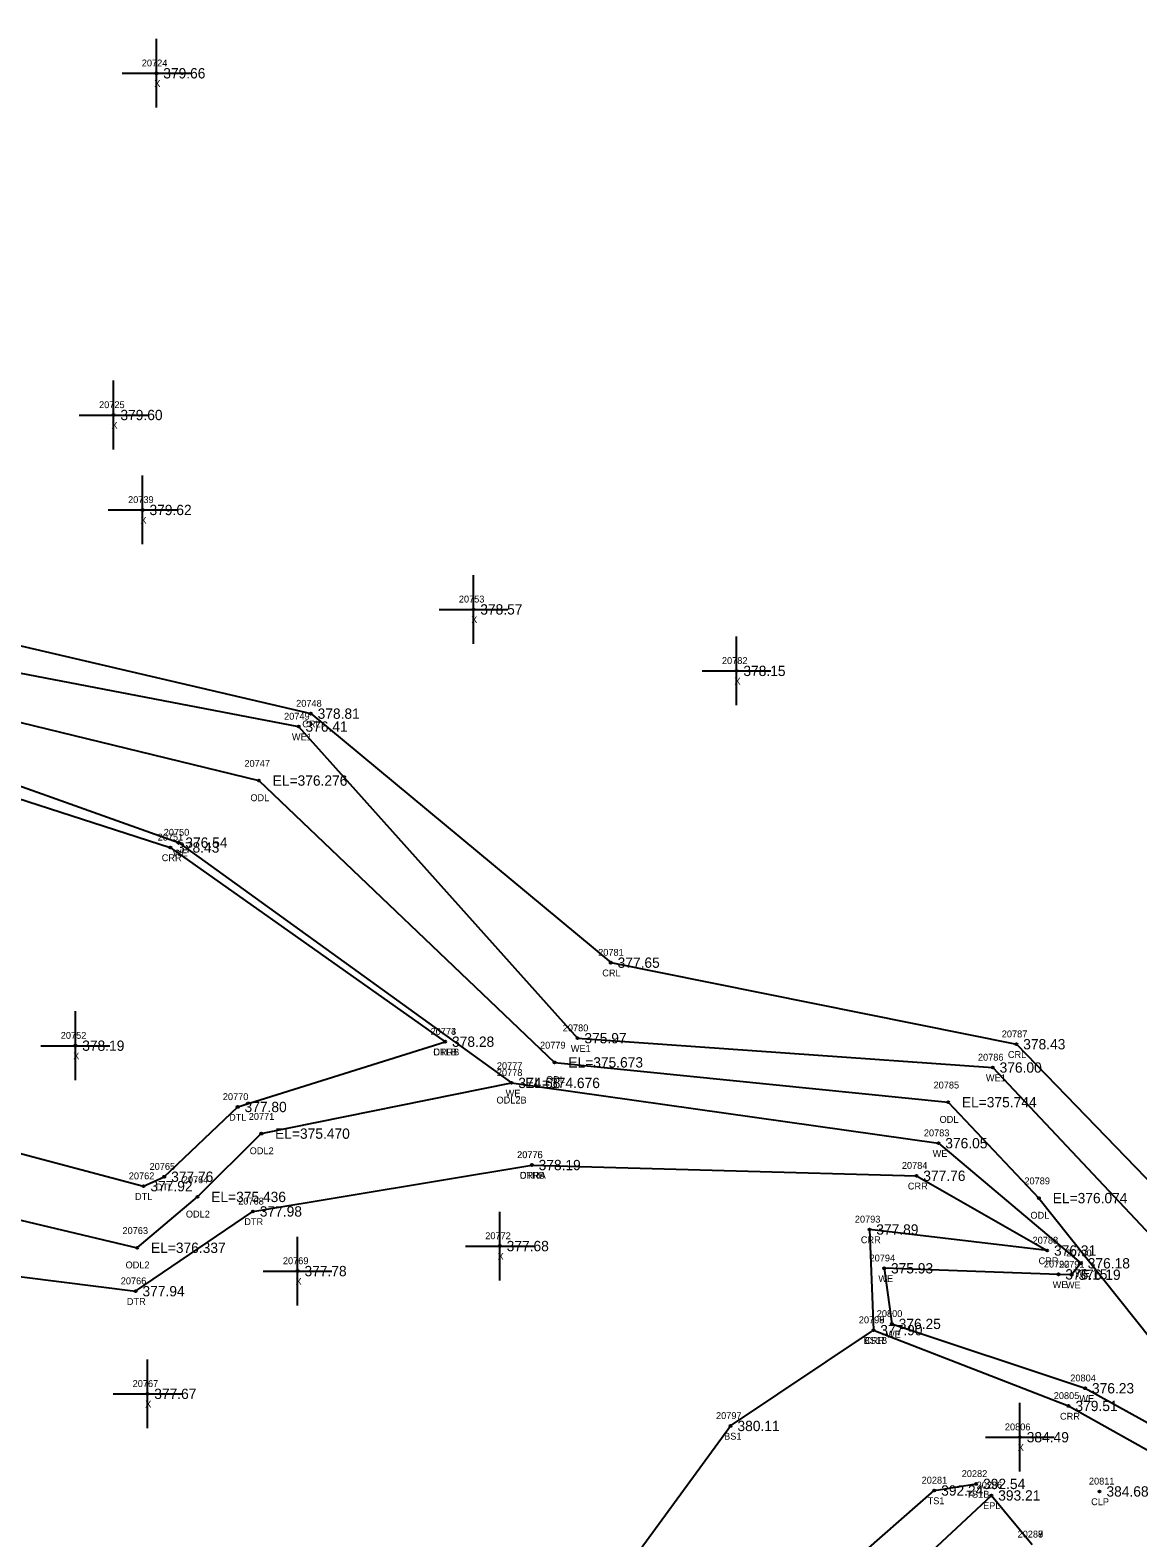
# Model space of a CAD drawing. Extents: x 2116373 to 2118139, y 979529 to 981026.
# Drawn here: x 2117180.8 to 2117341.9, y 980127.3 to 980346.7 of the extents above; entities that cross this region are included whole.
import ezdxf

# ---------------------------------------------------------------- set-up
doc = ezdxf.new("R2010")
doc.units = 0
for name, color, linetype in [('RD_DTM_BkLn2', 7, 'Continuous'), ('RD_DTM_BkLn_txCode', 7, 'Continuous'), ('RD_EX_H2O', 7, 'Continuous'), ('RD_EX_H2O_txCode', 7, 'Continuous'), ('RD_EX_Misc', 7, 'Continuous'), ('RD_EX_Misc_txCode', 7, 'Continuous'), ('RD_EX_Road', 7, 'Continuous'), ('RD_EX_Road_txCode', 7, 'Continuous'), ('RD_EX_TX_H2O_ELEV', 7, 'Continuous'), ('RD_EX_TX_Misc_ELEV', 7, 'Continuous'), ('RD_EX_TX_Road_ELEV', 7, 'Continuous'), ('RD_HC_Survey_ELEV', 7, 'Continuous'), ('RD_HC_Survey_txCode', 7, 'Continuous'), ('RD_SMD_Locator', 7, 'Continuous')]:
    doc.layers.add(name, color=color, linetype=linetype)

msp = doc.modelspace()

# ---------------------------------------------------------------- linework, layer by layer
at = {"layer": 'RD_DTM_BkLn2'}
for points in [[(2117265.44, 980120.03), (2117282.69, 980143.6), (2117303.47, 980157.54)], [(2116410.78, 979641.79), (2116465.45, 979654.97), (2116518.83, 979664.89), (2116614.96, 979683.75), (2116663.75, 979692.58), (2116713.02, 979705.22), (2116760.07, 979721.97), (2116804.88, 979741.47), (2116850.79, 979761.38), (2116894.83, 979783.88), (2116937.98, 979807.44), (2116977.39, 979833.6), (2117020.56, 979865.29), (2117056.86, 979896.38), (2117094.29, 979932.2), (2117168.14, 979997.38), (2117238.71, 980069.61), (2117312.33, 980134.21), (2117318.43, 980135.16)]]:
    msp.add_lwpolyline(points, dxfattribs=at)
at = {"layer": 'RD_EX_H2O'}
for points in [[(2117055.27, 980533.4), (2117084.87, 980468.5), (2117113.12, 980396.82), (2117150.26, 980360.48), (2117172.14, 980330.53), (2117167.4, 980300.56), (2117152, 980282.05), (2117153.33, 980268.31), (2117164.01, 980260.72), (2117221.6, 980247.26), (2117265.25, 980211.02), (2117324.27, 980199.15), (2117347.37, 980175.31), (2117365.85, 980182.55), (2117389.45, 980162.29), (2117399.63, 980142.01), (2117411.26, 980120.88), (2117420.42, 980068.64), (2117446.24, 980057.21), (2117497.11, 980045.39), (2117594.71, 979999.33), (2117646.33, 979985.56), (2117750.91, 980032.44), (2117805.09, 980018.87)], [(2117050.82, 980532.07), (2117080.88, 980466.55), (2117110.64, 980395.71), (2117144.25, 980349.68), (2117164.75, 980337.49), (2117167.1, 980320.28), (2117162.85, 980307.87), (2117148.28, 980284.4), (2117152.02, 980266.59), (2117158.19, 980257.22), (2117219.84, 980245.38), (2117260.42, 980200.03), (2117320.83, 980195.76), (2117348.44, 980166.4)], [(2117046.35, 980528.47), (2117072.74, 980464.26), (2117103.18, 980398.05), (2117142.6, 980347.56), (2117158.28, 980333.4), (2117157.84, 980320.26), (2117155.72, 980311.74), (2117145.74, 980285.73), (2117146.15, 980263.73), (2117154.31, 980252.06), (2117214.06, 980237.52), (2117257.08, 980196.51), (2117314.34, 980190.71), (2117327.56, 980176.76), (2117343.89, 980156.23)], [(2117042.29, 980526.09), (2117065.56, 980461.15), (2117099.14, 980397), (2117139.48, 980344.65), (2117153.05, 980329.52), (2117152.49, 980324.98), (2117153.14, 980319.82), (2117152.6, 980312.45), (2117140.5, 980286.71), (2117130.05, 980269.91), (2117147.41, 980248.1), (2117202.36, 980228.49), (2117250.8, 980193.52), (2117312.93, 980184.75), (2117333.66, 980167.27), (2117332.31, 980165.61), (2117330.39, 980165.66), (2117305.03, 980166.54), (2117306.15, 980158.45), (2117334.27, 980149.08), (2117359.88, 980134.92)], [(2117031.59, 980522.05), (2117061.22, 980460.91), (2117085.86, 980397.22), (2117136.43, 980344.22), (2117150.07, 980329.14), (2117146.87, 980313.29), (2117136.68, 980286.81), (2117127.11, 980271.21), (2117134.99, 980253.7), (2117146.93, 980245.3), (2117201.17, 980227.79), (2117241.16, 980199.52)], [(2117108.2, 980200.33), (2117129.82, 980185.32), (2117196.35, 980169.53), (2117205.12, 980176.93), (2117214.41, 980186.14), (2117250.8, 980193.52)], [(2117108.2, 980200.33), (2117119.12, 980172.91), (2117196.12, 980163.21), (2117213.19, 980174.82), (2117253.76, 980181.57)], [(2117108.2, 980200.33), (2117128.09, 980196.89), (2117197.27, 980178.49), (2117200.29, 980179.87), (2117210.97, 980190.02), (2117241.16, 980199.52)], [(2117253.76, 980181.57), (2117309.73, 980180.01), (2117328.75, 980169.13), (2117302.89, 980172.19), (2117303.47, 980157.54), (2117331.87, 980146.51), (2117356.54, 980132.72), (2117379.52, 980112.38), (2117402.94, 980061.78), (2117424.79, 980029.41), (2117490.12, 980015.27), (2117551.05, 979984.61)]]:
    msp.add_lwpolyline(points, dxfattribs=at)
at = {"layer": 'RD_EX_Misc'}
for p, q in [((2117199.14, 980335.45), (2117199.14, 980345.45)), ((2117194.14, 980340.45), (2117204.14, 980340.45)), ((2117192.91, 980285.72), (2117192.91, 980295.72)), ((2117187.91, 980290.72), (2117197.91, 980290.72)), ((2117197.14, 980271.9), (2117197.14, 980281.9)), ((2117192.14, 980276.9), (2117202.14, 980276.9)), ((2117245.27, 980257.43), (2117245.27, 980267.43)), ((2117240.27, 980262.43), (2117250.27, 980262.43)), ((2117283.55, 980248.48), (2117283.55, 980258.48)), ((2117278.55, 980253.48), (2117288.55, 980253.48)), ((2117187.35, 980193.94), (2117187.35, 980203.94)), ((2117182.35, 980198.94), (2117192.35, 980198.94)), ((2117249.11, 980164.78), (2117249.11, 980174.78)), ((2117219.69, 980161.14), (2117219.69, 980171.14)), ((2117244.11, 980169.78), (2117254.11, 980169.78)), ((2117214.69, 980166.14), (2117224.69, 980166.14)), ((2117197.83, 980143.27), (2117197.83, 980153.27)), ((2117192.83, 980148.27), (2117202.83, 980148.27)), ((2117324.78, 980136.96), (2117324.78, 980146.96)), ((2117319.78, 980141.96), (2117329.78, 980141.96))]:
    msp.add_line(p, q, dxfattribs=at)
at = {"layer": 'RD_EX_Road'}
msp.add_lwpolyline([(2116412.2, 979638.84), (2116468.17, 979651.36), (2116519.2, 979662.5), (2116617.24, 979678.85), (2116665.51, 979689.1), (2116714.23, 979702.46), (2116761.42, 979719.35), (2116806.99, 979737.42), (2116852.23, 979758.11), (2116896.57, 979780.91), (2116939.1, 979805.52), (2116978.46, 979832.1), (2117021.29, 979863.87), (2117058.15, 979895.61), (2117096.06, 979930.47), (2117170.14, 979995.71), (2117244.91, 980062.82), (2117320.63, 980133.49), (2117326.56, 980126.36)], dxfattribs=at)
at = {"layer": 'RD_SMD_Locator'}
for centre in [(2117199.14, 980340.45), (2117192.91, 980290.72), (2117197.14, 980276.9), (2117245.27, 980262.43), (2117283.55, 980253.48), (2117221.6, 980247.26), (2117219.84, 980245.38), (2117214.06, 980237.52), (2117201.17, 980227.79), (2117202.36, 980228.49), (2117265.25, 980211.02), (2117187.35, 980198.94), (2117241.16, 980199.52), (2117241.16, 980199.52), (2117260.42, 980200.03), (2117324.27, 980199.15), (2117257.08, 980196.51), (2117320.83, 980195.76), (2117250.8, 980193.52), (2117250.8, 980193.52), (2117210.97, 980190.02), (2117314.34, 980190.71), (2117214.41, 980186.14), (2117312.93, 980184.75), (2117253.76, 980181.57), (2117253.76, 980181.57), (2117200.29, 980179.87), (2117309.73, 980180.01), (2117197.27, 980178.49), (2117205.12, 980176.93), (2117327.56, 980176.76), (2117213.19, 980174.82), (2117302.89, 980172.19), (2117196.35, 980169.53), (2117249.11, 980169.78), (2117328.75, 980169.13), (2117219.69, 980166.14), (2117305.03, 980166.54), (2117333.66, 980167.27), (2117330.39, 980165.66), (2117332.31, 980165.61), (2117196.12, 980163.21), (2117303.47, 980157.54), (2117303.47, 980157.54), (2117306.15, 980158.45), (2117197.83, 980148.27), (2117334.27, 980149.08), (2117331.87, 980146.51), (2117282.69, 980143.6), (2117324.78, 980141.96), (2117318.43, 980135.16), (2117312.33, 980134.21), (2117320.63, 980133.49), (2117336.38, 980134.07)]:
    msp.add_circle(centre, 0.15, dxfattribs=at)

# ---------------------------------------------------------------- texts
at = {"layer": 'RD_DTM_BkLn_txCode'}
for s, p in [('20798', (2117301.35, 980158.54)), ('BS1B', (2117302.06, 980155.54)), ('20797', (2117280.57, 980144.6)), ('BS1', (2117281.75, 980141.6)), ('20281', (2117310.49, 980135.21)), ('20282', (2117316.32, 980136.16)), ('TS1', (2117311.36, 980132.21)), ('TS1B', (2117317, 980133.16))]:
    msp.add_text(s, height=1, dxfattribs=at).set_placement(p)
at = {"layer": 'RD_EX_H2O_txCode'}
for s, p in [('20748', (2117219.48, 980248.26)), ('20749', (2117217.72, 980246.38)), ('CRL', (2117220.37, 980245.26)), ('WE1', (2117218.86, 980243.38)), ('20747', (2117211.95, 980239.52)), ('ODL', (2117212.82, 980234.52)), ('20751', (2117199.33, 980228.79)), ('20750', (2117200.21, 980229.49)), ('WE', (2117201.53, 980226.49)), ('CRR', (2117199.92, 980225.79)), ('20781', (2117263.42, 980212.02)), ('CRL', (2117264.02, 980209.02)), ('20773', (2117239.04, 980200.52)), ('20774', (2117239.04, 980200.52)), ('20780', (2117258.27, 980201.03)), ('20787', (2117322.15, 980200.15)), ('20779', (2117254.96, 980198.51)), ('WE1', (2117259.44, 980198.03)), ('CRRB', (2117239.43, 980197.52)), ('DTLB', (2117239.44, 980197.52)), ('20777', (2117248.68, 980195.52)), ('20786', (2117318.68, 980196.76)), ('CRL', (2117323.04, 980197.15)), ('20778', (2117248.68, 980194.52)), ('ODL', (2117255.84, 980193.51)), ('WE1', (2117319.84, 980193.76)), ('WE', (2117249.96, 980191.52)), ('20785', (2117312.22, 980192.71)), ('20770', (2117208.81, 980191.02)), ('ODL2B', (2117248.63, 980190.52)), ('DTL', (2117209.72, 980188.02)), ('20771', (2117212.58, 980188.14)), ('ODL', (2117313.1, 980187.71)), ('20783', (2117310.81, 980185.75)), ('ODL2', (2117212.72, 980183.14)), ('20776', (2117251.62, 980182.57)), ('20775', (2117251.64, 980182.57)), ('WE', (2117312.09, 980182.75)), ('20765', (2117198.15, 980180.87)), ('20784', (2117307.61, 980181.01)), ('20762', (2117195.13, 980179.49)), ('20764', (2117202.98, 980178.93)), ('CRRA', (2117252.02, 980179.57)), ('DTRB', (2117252.02, 980179.57)), ('CRR', (2117308.48, 980178.01)), ('20789', (2117325.44, 980178.76)), ('DTL', (2117196.03, 980176.49)), ('DTL', (2117199.05, 980177.87)), ('20768', (2117211.05, 980175.82)), ('ODL2', (2117203.43, 980173.93)), ('ODL', (2117326.32, 980173.76)), ('20763', (2117194.21, 980171.53)), ('DTR', (2117211.93, 980172.82)), ('20793', (2117300.77, 980173.19)), ('CRR', (2117301.64, 980170.19)), ('20788', (2117326.63, 980170.13)), ('20794', (2117302.91, 980167.54)), ('CRR', (2117327.5, 980167.13)), ('20790', (2117331.51, 980168.27)), ('ODL2', (2117194.66, 980166.53)), ('20792', (2117328.27, 980166.66)), ('20791', (2117330.47, 980166.61)), ('WE', (2117332.82, 980165.27)), ('20766', (2117193.96, 980164.21)), ('WE', (2117304.19, 980164.54)), ('WE', (2117329.55, 980163.66)), ('WE', (2117331.47, 980163.61)), ('DTR', (2117194.85, 980161.21)), ('20799', (2117301.35, 980158.54)), ('20800', (2117303.96, 980159.45)), ('WE', (2117305.31, 980156.45)), ('CRR', (2117302.22, 980155.54)), ('20804', (2117332.12, 980150.08)), ('20805', (2117329.71, 980147.51)), ('WE', (2117333.43, 980147.08)), ('CRR', (2117330.62, 980144.51))]:
    msp.add_text(s, height=1, dxfattribs=at).set_placement(p)
at = {"layer": 'RD_EX_Misc_txCode'}
for s, p in [('20724', (2117197.02, 980341.45)), ('X', (2117198.83, 980338.45)), ('20725', (2117190.8, 980291.72)), ('X', (2117192.6, 980288.72)), ('20739', (2117195.02, 980277.9)), ('X', (2117196.82, 980274.9)), ('20753', (2117243.15, 980263.43)), ('X', (2117244.95, 980260.43)), ('20782', (2117281.43, 980254.48)), ('X', (2117283.24, 980251.48)), ('20752', (2117185.23, 980199.94)), ('X', (2117187.04, 980196.94)), ('20772', (2117246.99, 980170.78)), ('20769', (2117217.55, 980167.14)), ('X', (2117248.79, 980167.78)), ('X', (2117219.38, 980164.14)), ('20767', (2117195.69, 980149.27)), ('X', (2117197.51, 980146.27)), ('20806', (2117322.6, 980142.96)), ('X', (2117324.47, 980139.96))]:
    msp.add_text(s, height=1, dxfattribs=at).set_placement(p)
at = {"layer": 'RD_EX_Road_txCode'}
for s, p in [('20286', (2117318.49, 980134.49)), ('EPL', (2117319.43, 980131.49)), ('20287', (2117324.45, 980127.36)), ('20288', (2117324.45, 980127.36))]:
    msp.add_text(s, height=1, dxfattribs=at).set_placement(p)
at = {"layer": 'RD_EX_TX_H2O_ELEV'}
for s, p in [('378.81', (2117222.6, 980246.51)), ('376.41', (2117220.84, 980244.63)), ('EL=376.276', (2117216.06, 980236.77)), ('378.43', (2117202.17, 980227.04)), ('376.54', (2117203.36, 980227.74)), ('377.65', (2117266.25, 980210.27)), ('378.28', (2117242.16, 980198.77)), ('378.28', (2117242.16, 980198.77)), ('375.97', (2117261.42, 980199.28)), ('378.43', (2117325.27, 980198.4)), ('EL=375.673', (2117259.08, 980195.76)), ('376.00', (2117321.83, 980195.01)), ('374.68', (2117251.8, 980192.77)), ('EL=374.676', (2117252.8, 980192.77)), ('377.80', (2117211.97, 980189.27)), ('EL=375.744', (2117316.34, 980189.96)), ('EL=375.470', (2117216.41, 980185.39)), ('376.05', (2117313.93, 980184)), ('378.19', (2117254.76, 980180.82)), ('378.19', (2117254.76, 980180.82)), ('377.92', (2117198.27, 980177.74)), ('377.76', (2117201.29, 980179.12)), ('377.76', (2117310.73, 980179.26)), ('EL=375.436', (2117207.12, 980176.18)), ('EL=376.074', (2117329.56, 980176.01)), ('377.98', (2117214.19, 980174.07)), ('377.89', (2117303.89, 980171.44)), ('EL=376.337', (2117198.35, 980168.78)), ('376.31', (2117329.75, 980168.38)), ('376.18', (2117334.66, 980166.52)), ('375.93', (2117306.03, 980165.79)), ('376.15', (2117331.39, 980164.91)), ('376.19', (2117333.31, 980164.86)), ('377.94', (2117197.12, 980162.46)), ('377.90', (2117304.47, 980156.79)), ('376.25', (2117307.15, 980157.7)), ('376.23', (2117335.27, 980148.33)), ('379.51', (2117332.87, 980145.76))]:
    msp.add_text(s, height=1.5, dxfattribs=at).set_placement(p)
at = {"layer": 'RD_EX_TX_Misc_ELEV'}
for s, p in [('379.66', (2117200.14, 980339.7)), ('379.60', (2117193.91, 980289.97)), ('379.62', (2117198.14, 980276.15)), ('378.57', (2117246.27, 980261.68)), ('378.15', (2117284.55, 980252.73)), ('378.19', (2117188.35, 980198.19)), ('377.68', (2117250.11, 980169.03)), ('377.78', (2117220.69, 980165.39)), ('377.90', (2117304.47, 980156.79)), ('377.67', (2117198.83, 980147.52)), ('380.11', (2117283.69, 980142.85)), ('384.49', (2117325.78, 980141.21)), ('392.54', (2117319.43, 980134.41)), ('392.24', (2117313.33, 980133.46))]:
    msp.add_text(s, height=1.5, dxfattribs=at).set_placement(p)
at = {"layer": 'RD_EX_TX_Road_ELEV'}
msp.add_text('393.21', height=1.5, dxfattribs=at).set_placement((2117321.63, 980132.74))
at = {"layer": 'RD_HC_Survey_ELEV'}
msp.add_text('384.68', height=1.5, dxfattribs=at).set_placement((2117337.38, 980133.32))
at = {"layer": 'RD_HC_Survey_txCode'}
for s, p in [('20811', (2117334.83, 980135.07)), ('CLP', (2117335.15, 980132.07)), ('20289', (2117324.45, 980127.36))]:
    msp.add_text(s, height=1, dxfattribs=at).set_placement(p)

doc.saveas('drawing.dxf')
